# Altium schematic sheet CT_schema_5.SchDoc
size 385 x 185 mm
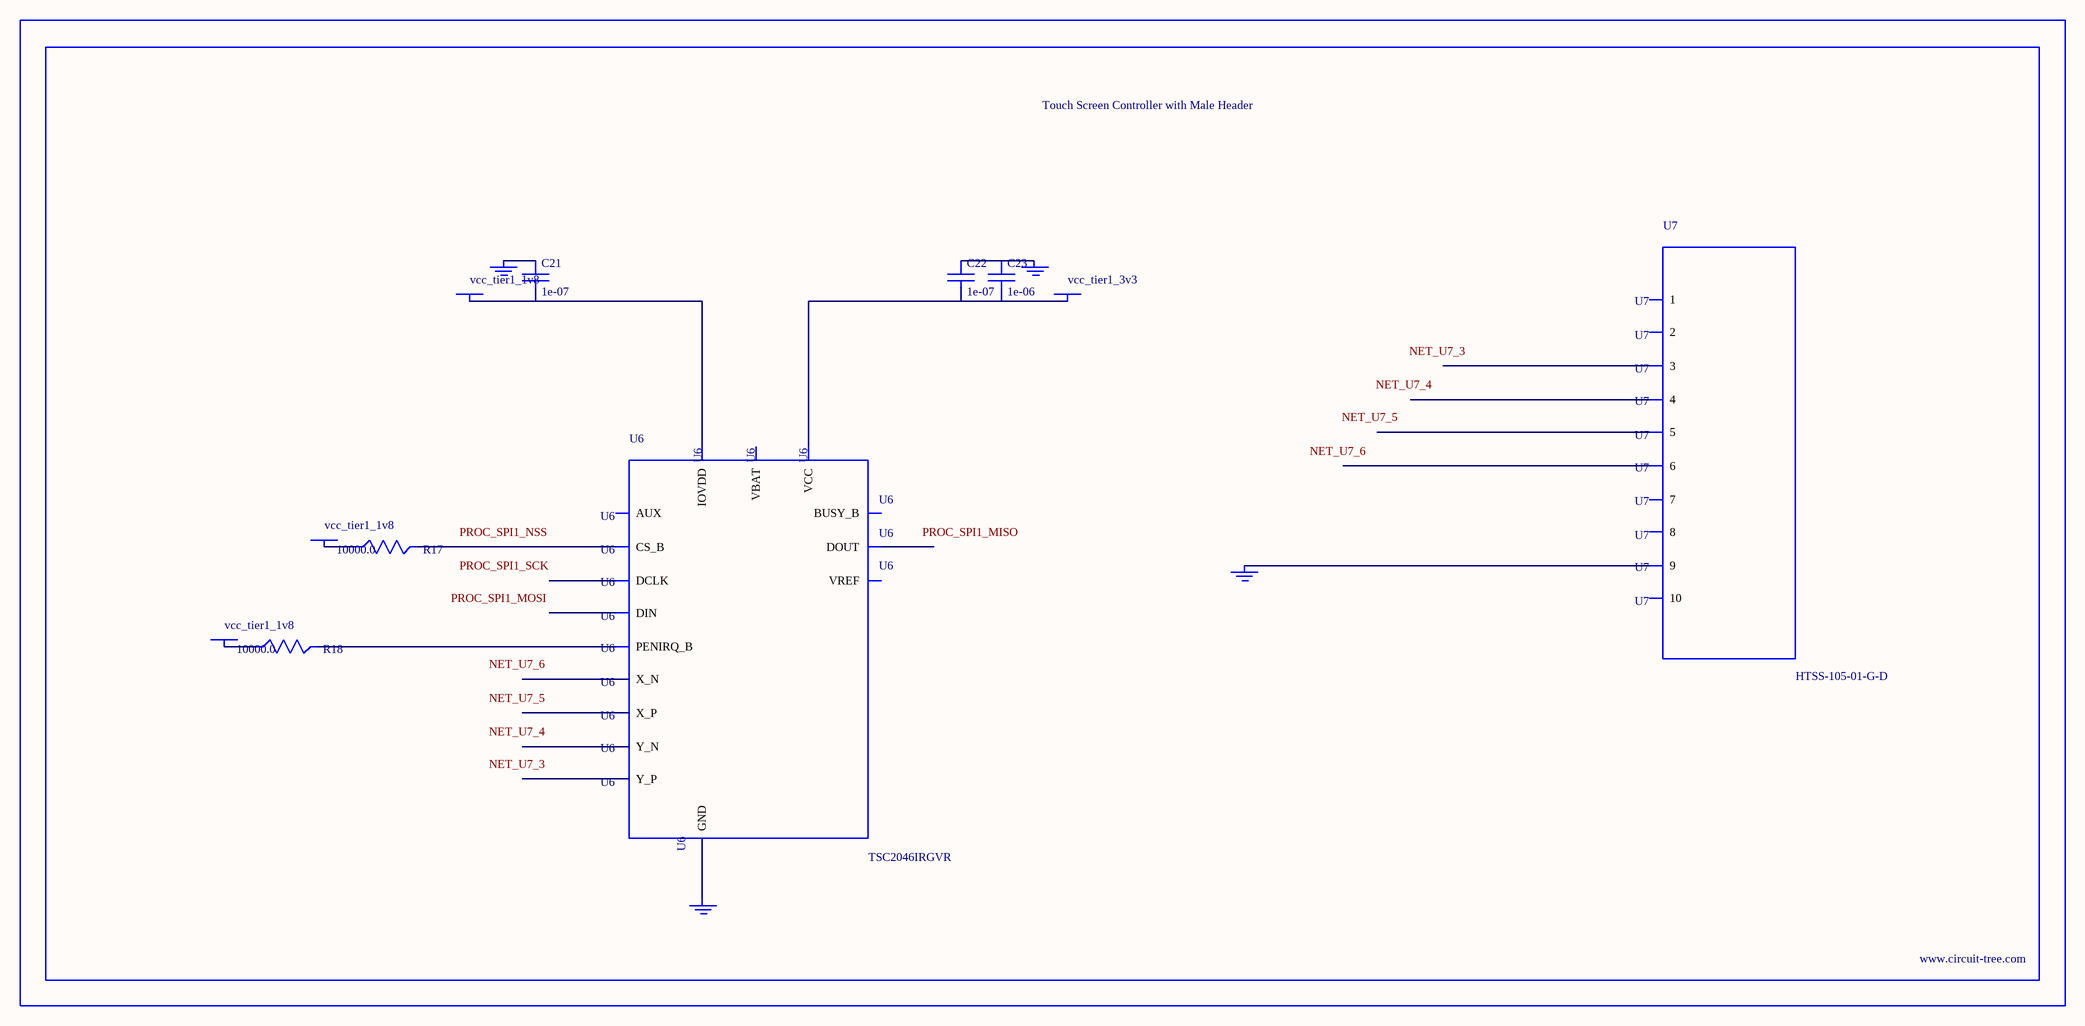
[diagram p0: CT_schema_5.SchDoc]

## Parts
BORDER4  (no value)
C21  1e-07  [C0402]
C22  1e-07  [C0402]
C23  1e-06  [C0603]
GND_INSTANCE_4_0  (no value)
GND_INSTANCE_4_1  (no value)
GND_INSTANCE_4_2  (no value)
GND_INSTANCE_4_3  (no value)
POWER_INSTANCE_4_0  vcc_tier1_1v8
POWER_INSTANCE_4_1  vcc_tier1_3v3
POWER_INSTANCE_4_2  vcc_tier1_1v8
POWER_INSTANCE_4_3  vcc_tier1_1v8
R17  10000.0  [R0603]
R18  10000.0  [R0603]
U6  TSC2046IRGVR  [VQFN-16]
U7  HTSS-105-01-G-D  [HTSS-105-01-G-D]

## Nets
NetC21_1: C21.1 GND_INSTANCE_4_1.0(GND)
NetC21_2: C21.2 POWER_INSTANCE_4_2.0(PWR) U6.14(IOVDD)
NetC22_1: C22.1 C23.1 GND_INSTANCE_4_0.0(GND)
NetC22_2: C22.2 C23.2 POWER_INSTANCE_4_1.0(PWR) U6.5(VCC)
NetGND_INSTANCE_4_2_0: GND_INSTANCE_4_2.0(GND) U6.10(GND)
NetGND_INSTANCE_4_3_0: GND_INSTANCE_4_3.0(GND) U7.9
NetPOWER_INSTANCE_4_0_0: POWER_INSTANCE_4_0.0(PWR) R17.1
NetPOWER_INSTANCE_4_3_0: POWER_INSTANCE_4_3.0(PWR) R18.1
NetR17_2: R17.2 U6.3(CS_B)
NetR18_2: R18.2 U6.15(PENIRQ_B)

Not connected (* = marked no-connect by the designer): U6 1(BUSY_B) 2(DIN) 4(DCLK) 6(X_P) 7(Y_P) 8(X_N) 9(Y_N) 11(VBAT) 12(AUX) 13(VREF) 16(DOUT); U7 1 2 3 4 5 6 7 8 10

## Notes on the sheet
- Labels drawn without touching a wire or pin: NET_U7_3, NET_U7_4, NET_U7_5, NET_U7_6, PROC_SPI1_MISO, PROC_SPI1_MOSI, PROC_SPI1_NSS, PROC_SPI1_SCK

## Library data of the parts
BORDER4 = BORDER_PAGE4
C21 C22 = C0402C104K3RACTU
C23 = C0603C105K3RACTU
GND_INSTANCE_4_0-GND_INSTANCE_4_3 = GND
POWER_INSTANCE_4_0-POWER_INSTANCE_4_3 = PWR
R17 R18 = RC0603JR-0710KL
